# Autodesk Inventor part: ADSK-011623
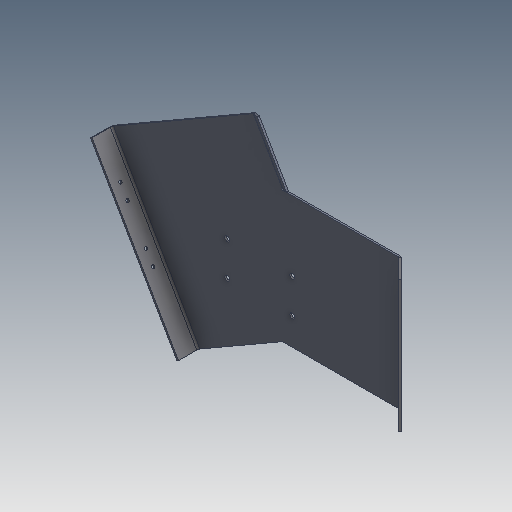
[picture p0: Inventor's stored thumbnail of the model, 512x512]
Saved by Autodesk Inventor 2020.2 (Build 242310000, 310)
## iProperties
Created: 2000-02
Part Number: ADSK-011623
Document SubType Name: Modeling
Designer: sspink
Material: Pearson Stainless Steel
Density: 8.03 g/cm^3
Sheet Metal Rule: Standard
Appearance: Pearson-Stainless
Mass: 3530.26 g
Surface Area: 2988.13 cm^2
Volume: 439.634 cm^3
Control State: 0
Master: False
Checked Out: False
Shininess: 57.0
Length Units: 11272
Angle Units: 11279
Time Units: 11290
Mass Units: 11286
Length Display Precision: 3
Angle Display Precision: 2
Compacted: True
Cutlength: (20.25 X 34.75) 704 SI
Material Desc: SHEET,HRS,11 GA
Material_Number: Axxxxxx
Dimensions: 16,5x1,5x21,3 in
Mass: 7,783 lb
VLT_Material: Pearson Stainless Steel
Density: 8.03
Volumn: 528.1082511778134
Area: 3389.6779900047272
PropertySet Name: Model Information
Author: sspink
Revision Number: -
Title: ADSK-011623
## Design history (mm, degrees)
derived "ADSK-011624.ipt"
node "Solide1"
node "Corps solides"
node "Corps surfaciques"
feature "Solide1::ADSK-011624.ipt" dims "d47" = 10
tag "Bezeichnung1"
node "Volumenkörper2"
other parameters: "Thickness" = 3.175, "BendRadius" = 3.175 (= Thickness), "BendReliefWidth" = 3.175 (= Thickness), "BendReliefDepth" = 1.5875 (= 0.5 x Thickness), "CornerReliefSize" = 7.14375 (= 2.25 x Thickness), "SeamGap" = 0.00508, "MinimumRemnant" = 6.35 (= 2 x Thickness), "d2" = 3.175 (= BendRadius), "TransitionRadius" = 3.175 (= BendRadius), "TailleRayonJacobi" = 3.175 (= Thickness), "TailleJeu" = 3.175 (= Thickness)
